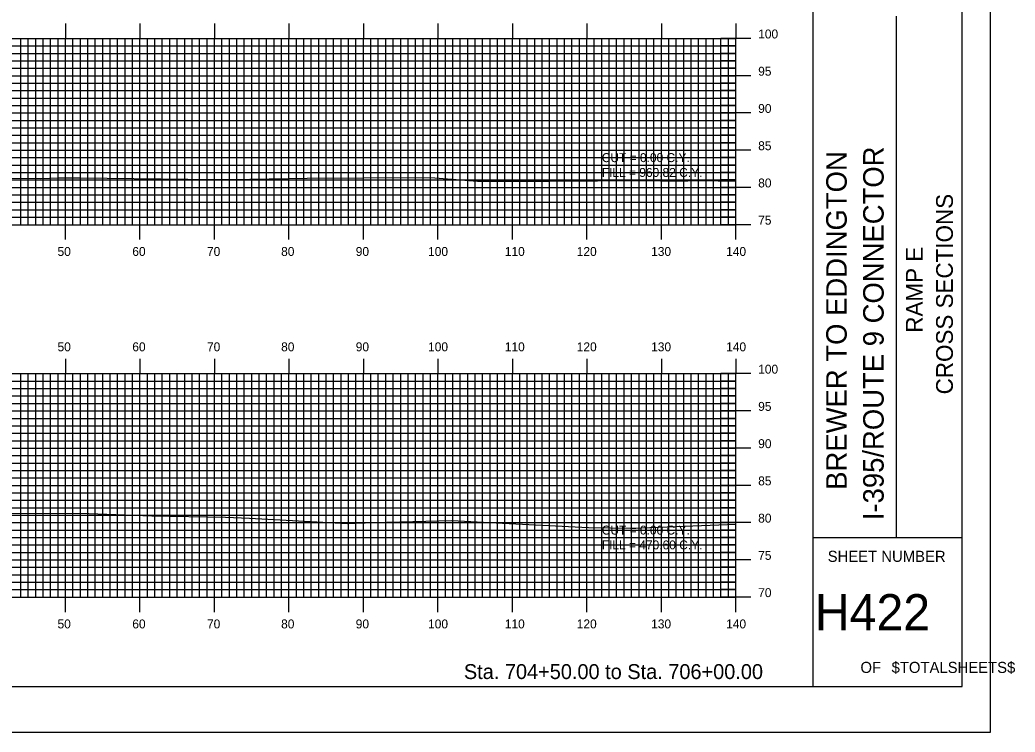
# Model space of a CAD drawing. Extents: x 853723 to 854066, y 364366 to 364586.
# Drawn here: x 853932.6 to 854066.2, y 364365.7 to 364461.3 of the extents above; entities that cross this region are included whole.
import ezdxf

# ---------------------------------------------------------------- set-up
doc = ezdxf.new("R2010")
doc.units = 0
for name, color, linetype in [('BORDER', 7, 'Continuous'), ('D_Text_Standard', 7, 'Continuous'), ('H_V ANNOTATION', 7, 'Continuous'), ('MAJOR', 7, 'Continuous'), ('MINOR', 7, 'Continuous'), ('PLOT BOUNDARY', 7, 'Continuous'), ('S_Roadway_Centerline', 7, 'Continuous')]:
    doc.layers.add(name, color=color, linetype=linetype)

msp = doc.modelspace()

# ---------------------------------------------------------------- linework, layer by layer
at = {"layer": 'BORDER'}
for p, q in [((854039.12, 364371.79), (854039.12, 364581.79)), ((854050.3, 364391.79), (854050.3, 364461.79)), ((854039.12, 364391.79), (854059.12, 364391.79))]:
    msp.add_line(p, q, dxfattribs=at)
msp.add_lwpolyline([(853739.12, 364371.79), (854059.12, 364371.79), (854059.12, 364581.79), (853739.12, 364581.79)], close=True, dxfattribs=at)
at = {"layer": 'MAJOR'}
for p, q in [((853938.72, 364460.79), (853938.72, 364458.79)), ((853948.72, 364460.79), (853948.72, 364458.79)), ((853958.72, 364460.79), (853958.72, 364458.79)), ((853968.72, 364460.79), (853968.72, 364458.79)), ((853978.72, 364460.79), (853978.72, 364458.79)), ((853988.72, 364460.79), (853988.72, 364458.79)), ((853998.72, 364460.79), (853998.72, 364458.79)), ((854008.72, 364460.79), (854008.72, 364458.79)), ((854018.72, 364460.79), (854018.72, 364458.79)), ((854028.72, 364460.79), (854028.72, 364458.79)), ((853748.72, 364458.79), (854028.72, 364458.79)), ((853748.72, 364458.79), (854028.72, 364458.79)), ((853938.72, 364433.79), (853938.72, 364458.79)), ((853948.72, 364433.79), (853948.72, 364458.79)), ((853958.72, 364433.79), (853958.72, 364458.79)), ((853968.72, 364433.79), (853968.72, 364458.79)), ((853978.72, 364433.79), (853978.72, 364458.79)), ((853988.72, 364433.79), (853988.72, 364458.79)), ((853998.72, 364433.79), (853998.72, 364458.79)), ((854008.72, 364433.79), (854008.72, 364458.79)), ((854018.72, 364433.79), (854018.72, 364458.79)), ((854030.72, 364458.79), (854026.71, 364458.79)), ((854028.72, 364433.79), (854028.72, 364458.79)), ((854028.72, 364433.79), (854028.72, 364458.79)), ((853748.72, 364453.79), (854028.72, 364453.79)), ((854030.72, 364453.79), (854026.71, 364453.79)), ((853748.72, 364448.79), (854028.72, 364448.79)), ((854030.72, 364448.79), (854026.71, 364448.79)), ((853748.72, 364443.79), (854028.72, 364443.79)), ((854030.72, 364443.79), (854026.71, 364443.79)), ((853748.72, 364438.79), (854028.72, 364438.79)), ((854030.72, 364438.79), (854026.71, 364438.79)), ((853748.72, 364433.79), (854028.72, 364433.79)), ((853748.72, 364433.79), (854028.72, 364433.79)), ((853938.72, 364431.78), (853938.72, 364433.79)), ((853948.72, 364431.78), (853948.72, 364433.79)), ((853958.72, 364431.78), (853958.72, 364433.79)), ((853968.72, 364431.78), (853968.72, 364433.79)), ((853978.72, 364431.78), (853978.72, 364433.79)), ((853988.72, 364431.78), (853988.72, 364433.79)), ((853998.72, 364431.78), (853998.72, 364433.79)), ((854008.72, 364431.78), (854008.72, 364433.79)), ((854018.72, 364431.78), (854018.72, 364433.79)), ((854030.72, 364433.79), (854026.71, 364433.79)), ((854028.72, 364431.78), (854028.72, 364433.79)), ((853938.72, 364415.79), (853938.72, 364413.79)), ((853948.72, 364415.79), (853948.72, 364413.79)), ((853958.72, 364415.79), (853958.72, 364413.79)), ((853968.72, 364415.79), (853968.72, 364413.79)), ((853978.72, 364415.79), (853978.72, 364413.79)), ((853988.72, 364415.79), (853988.72, 364413.79)), ((853998.72, 364415.79), (853998.72, 364413.79)), ((854008.72, 364415.79), (854008.72, 364413.79)), ((854018.72, 364415.79), (854018.72, 364413.79)), ((854028.72, 364415.79), (854028.72, 364413.79)), ((853748.72, 364413.79), (854028.72, 364413.79)), ((853748.72, 364413.79), (854028.72, 364413.79)), ((853938.72, 364383.79), (853938.72, 364413.79)), ((853948.72, 364383.79), (853948.72, 364413.79)), ((853958.72, 364383.79), (853958.72, 364413.79)), ((853968.72, 364383.79), (853968.72, 364413.79)), ((853978.72, 364383.79), (853978.72, 364413.79)), ((853988.72, 364383.79), (853988.72, 364413.79)), ((853998.72, 364383.79), (853998.72, 364413.79)), ((854008.72, 364383.79), (854008.72, 364413.79)), ((854018.72, 364383.79), (854018.72, 364413.79)), ((854030.72, 364413.79), (854026.71, 364413.79)), ((854028.72, 364383.79), (854028.72, 364413.79)), ((854028.72, 364383.79), (854028.72, 364413.79)), ((853748.72, 364408.79), (854028.72, 364408.79)), ((854030.72, 364408.79), (854026.71, 364408.79)), ((853748.72, 364403.79), (854028.72, 364403.79)), ((854030.72, 364403.79), (854026.71, 364403.79)), ((853748.72, 364398.79), (854028.72, 364398.79)), ((854030.72, 364398.79), (854026.71, 364398.79)), ((853748.72, 364393.79), (854028.72, 364393.79)), ((854030.72, 364393.79), (854026.71, 364393.79)), ((853748.72, 364388.79), (854028.72, 364388.79)), ((854030.72, 364388.79), (854026.71, 364388.79)), ((853748.72, 364383.79), (854028.72, 364383.79)), ((853748.72, 364383.79), (854028.72, 364383.79)), ((853938.72, 364381.78), (853938.72, 364383.79)), ((853948.72, 364381.78), (853948.72, 364383.79)), ((853958.72, 364381.78), (853958.72, 364383.79)), ((853968.72, 364381.78), (853968.72, 364383.79)), ((853978.72, 364381.78), (853978.72, 364383.79)), ((853988.72, 364381.78), (853988.72, 364383.79)), ((853998.72, 364381.78), (853998.72, 364383.79)), ((854008.72, 364381.78), (854008.72, 364383.79)), ((854018.72, 364381.78), (854018.72, 364383.79)), ((854030.72, 364383.79), (854026.71, 364383.79)), ((854028.72, 364381.78), (854028.72, 364383.79))]:
    msp.add_line(p, q, dxfattribs=at)
at = {"layer": 'MINOR'}
for p, q in [((853932.72, 364433.79), (853932.72, 364458.79)), ((853933.72, 364433.79), (853933.72, 364458.79)), ((853934.72, 364433.79), (853934.72, 364458.79)), ((853935.72, 364433.79), (853935.72, 364458.79)), ((853936.72, 364433.79), (853936.72, 364458.79)), ((853937.72, 364433.79), (853937.72, 364458.79)), ((853939.72, 364433.79), (853939.72, 364458.79)), ((853940.72, 364433.79), (853940.72, 364458.79)), ((853941.72, 364433.79), (853941.72, 364458.79)), ((853942.72, 364433.79), (853942.72, 364458.79)), ((853943.72, 364433.79), (853943.72, 364458.79)), ((853944.72, 364433.79), (853944.72, 364458.79)), ((853945.72, 364433.79), (853945.72, 364458.79)), ((853946.72, 364433.79), (853946.72, 364458.79)), ((853947.72, 364433.79), (853947.72, 364458.79)), ((853949.72, 364433.79), (853949.72, 364458.79)), ((853950.72, 364433.79), (853950.72, 364458.79)), ((853951.72, 364433.79), (853951.72, 364458.79)), ((853952.72, 364433.79), (853952.72, 364458.79)), ((853953.72, 364433.79), (853953.72, 364458.79)), ((853954.72, 364433.79), (853954.72, 364458.79)), ((853955.72, 364433.79), (853955.72, 364458.79)), ((853956.72, 364433.79), (853956.72, 364458.79)), ((853957.72, 364433.79), (853957.72, 364458.79)), ((853959.72, 364433.79), (853959.72, 364458.79)), ((853960.72, 364433.79), (853960.72, 364458.79)), ((853961.72, 364433.79), (853961.72, 364458.79)), ((853962.72, 364433.79), (853962.72, 364458.79)), ((853963.72, 364433.79), (853963.72, 364458.79)), ((853964.72, 364433.79), (853964.72, 364458.79)), ((853965.72, 364433.79), (853965.72, 364458.79)), ((853966.72, 364433.79), (853966.72, 364458.79)), ((853967.72, 364433.79), (853967.72, 364458.79)), ((853969.72, 364433.79), (853969.72, 364458.79)), ((853970.72, 364433.79), (853970.72, 364458.79)), ((853971.72, 364433.79), (853971.72, 364458.79)), ((853972.72, 364433.79), (853972.72, 364458.79)), ((853973.72, 364433.79), (853973.72, 364458.79)), ((853974.72, 364433.79), (853974.72, 364458.79)), ((853975.72, 364433.79), (853975.72, 364458.79)), ((853976.72, 364433.79), (853976.72, 364458.79)), ((853977.72, 364433.79), (853977.72, 364458.79)), ((853979.72, 364433.79), (853979.72, 364458.79)), ((853980.72, 364433.79), (853980.72, 364458.79)), ((853981.72, 364433.79), (853981.72, 364458.79)), ((853982.72, 364433.79), (853982.72, 364458.79)), ((853983.72, 364433.79), (853983.72, 364458.79)), ((853984.72, 364433.79), (853984.72, 364458.79)), ((853985.72, 364433.79), (853985.72, 364458.79)), ((853986.72, 364433.79), (853986.72, 364458.79)), ((853987.72, 364433.79), (853987.72, 364458.79)), ((853989.72, 364433.79), (853989.72, 364458.79)), ((853990.72, 364433.79), (853990.72, 364458.79)), ((853991.72, 364433.79), (853991.72, 364458.79)), ((853992.72, 364433.79), (853992.72, 364458.79)), ((853993.72, 364433.79), (853993.72, 364458.79)), ((853994.72, 364433.79), (853994.72, 364458.79)), ((853995.72, 364433.79), (853995.72, 364458.79)), ((853996.72, 364433.79), (853996.72, 364458.79)), ((853997.72, 364433.79), (853997.72, 364458.79)), ((853999.72, 364433.79), (853999.72, 364458.79)), ((854000.72, 364433.79), (854000.72, 364458.79)), ((854001.72, 364433.79), (854001.72, 364458.79)), ((854002.72, 364433.79), (854002.72, 364458.79)), ((854003.72, 364433.79), (854003.72, 364458.79)), ((854004.72, 364433.79), (854004.72, 364458.79)), ((854005.72, 364433.79), (854005.72, 364458.79)), ((854006.72, 364433.79), (854006.72, 364458.79)), ((854007.72, 364433.79), (854007.72, 364458.79)), ((854009.72, 364433.79), (854009.72, 364458.79)), ((854010.72, 364433.79), (854010.72, 364458.79)), ((854011.72, 364433.79), (854011.72, 364458.79)), ((854012.72, 364433.79), (854012.72, 364458.79)), ((854013.72, 364433.79), (854013.72, 364458.79)), ((854014.72, 364433.79), (854014.72, 364458.79)), ((854015.72, 364433.79), (854015.72, 364458.79)), ((854016.72, 364433.79), (854016.72, 364458.79)), ((854017.72, 364433.79), (854017.72, 364458.79)), ((854019.72, 364433.79), (854019.72, 364458.79)), ((854020.72, 364433.79), (854020.72, 364458.79)), ((854021.72, 364433.79), (854021.72, 364458.79)), ((854022.72, 364433.79), (854022.72, 364458.79)), ((854023.72, 364433.79), (854023.72, 364458.79)), ((854024.72, 364433.79), (854024.72, 364458.79)), ((854025.72, 364433.79), (854025.72, 364458.79)), ((854026.72, 364433.79), (854026.72, 364458.79)), ((854027.72, 364433.79), (854027.72, 364458.79)), ((853748.72, 364457.79), (854028.72, 364457.79)), ((853748.72, 364456.79), (854028.72, 364456.79)), ((854028.72, 364457.79), (854026.71, 364457.79)), ((854028.72, 364456.79), (854026.71, 364456.79)), ((853748.72, 364455.79), (854028.72, 364455.79)), ((854028.72, 364455.79), (854026.71, 364455.79)), ((853748.72, 364454.79), (854028.72, 364454.79)), ((854028.72, 364454.79), (854026.71, 364454.79)), ((853748.72, 364452.79), (854028.72, 364452.79)), ((854028.72, 364452.79), (854026.71, 364452.79)), ((853748.72, 364451.79), (854028.72, 364451.79)), ((854028.72, 364451.79), (854026.71, 364451.79)), ((853748.72, 364450.79), (854028.72, 364450.79)), ((854028.72, 364450.79), (854026.71, 364450.79)), ((853748.72, 364449.79), (854028.72, 364449.79)), ((854028.72, 364449.79), (854026.71, 364449.79)), ((853748.72, 364447.79), (854028.72, 364447.79)), ((854028.72, 364447.79), (854026.71, 364447.79)), ((853748.72, 364446.79), (854028.72, 364446.79)), ((854028.72, 364446.79), (854026.71, 364446.79)), ((853748.72, 364445.79), (854028.72, 364445.79)), ((853748.72, 364444.79), (854028.72, 364444.79)), ((854028.72, 364445.79), (854026.71, 364445.79)), ((854028.72, 364444.79), (854026.71, 364444.79)), ((853748.72, 364442.79), (854028.72, 364442.79)), ((854028.72, 364442.79), (854026.71, 364442.79)), ((853748.72, 364441.79), (854028.72, 364441.79)), ((853748.72, 364440.79), (854028.72, 364440.79)), ((854028.72, 364441.79), (854026.71, 364441.79)), ((854028.72, 364440.79), (854026.71, 364440.79)), ((853748.72, 364439.79), (854028.72, 364439.79)), ((854028.72, 364439.79), (854026.71, 364439.79)), ((853748.72, 364437.79), (854028.72, 364437.79)), ((853748.72, 364436.79), (854028.72, 364436.79)), ((854028.72, 364437.79), (854026.71, 364437.79)), ((854028.72, 364436.79), (854026.71, 364436.79)), ((853748.72, 364435.79), (854028.72, 364435.79)), ((854028.72, 364435.79), (854026.71, 364435.79)), ((853748.72, 364434.79), (854028.72, 364434.79)), ((854028.72, 364434.79), (854026.71, 364434.79)), ((853748.72, 364412.79), (854028.72, 364412.79)), ((853932.72, 364383.79), (853932.72, 364413.79)), ((853933.72, 364383.79), (853933.72, 364413.79)), ((853934.72, 364383.79), (853934.72, 364413.79)), ((853935.72, 364383.79), (853935.72, 364413.79)), ((853936.72, 364383.79), (853936.72, 364413.79)), ((853937.72, 364383.79), (853937.72, 364413.79)), ((853939.72, 364383.79), (853939.72, 364413.79)), ((853940.72, 364383.79), (853940.72, 364413.79)), ((853941.72, 364383.79), (853941.72, 364413.79)), ((853942.72, 364383.79), (853942.72, 364413.79)), ((853943.72, 364383.79), (853943.72, 364413.79)), ((853944.72, 364383.79), (853944.72, 364413.79)), ((853945.72, 364383.79), (853945.72, 364413.79)), ((853946.72, 364383.79), (853946.72, 364413.79)), ((853947.72, 364383.79), (853947.72, 364413.79)), ((853949.72, 364383.79), (853949.72, 364413.79)), ((853950.72, 364383.79), (853950.72, 364413.79)), ((853951.72, 364383.79), (853951.72, 364413.79)), ((853952.72, 364383.79), (853952.72, 364413.79)), ((853953.72, 364383.79), (853953.72, 364413.79)), ((853954.72, 364383.79), (853954.72, 364413.79)), ((853955.72, 364383.79), (853955.72, 364413.79)), ((853956.72, 364383.79), (853956.72, 364413.79)), ((853957.72, 364383.79), (853957.72, 364413.79)), ((853959.72, 364383.79), (853959.72, 364413.79)), ((853960.72, 364383.79), (853960.72, 364413.79)), ((853961.72, 364383.79), (853961.72, 364413.79)), ((853962.72, 364383.79), (853962.72, 364413.79)), ((853963.72, 364383.79), (853963.72, 364413.79)), ((853964.72, 364383.79), (853964.72, 364413.79)), ((853965.72, 364383.79), (853965.72, 364413.79)), ((853966.72, 364383.79), (853966.72, 364413.79)), ((853967.72, 364383.79), (853967.72, 364413.79)), ((853969.72, 364383.79), (853969.72, 364413.79)), ((853970.72, 364383.79), (853970.72, 364413.79)), ((853971.72, 364383.79), (853971.72, 364413.79)), ((853972.72, 364383.79), (853972.72, 364413.79)), ((853973.72, 364383.79), (853973.72, 364413.79)), ((853974.72, 364383.79), (853974.72, 364413.79)), ((853975.72, 364383.79), (853975.72, 364413.79)), ((853976.72, 364383.79), (853976.72, 364413.79)), ((853977.72, 364383.79), (853977.72, 364413.79)), ((853979.72, 364383.79), (853979.72, 364413.79)), ((853980.72, 364383.79), (853980.72, 364413.79)), ((853981.72, 364383.79), (853981.72, 364413.79)), ((853982.72, 364383.79), (853982.72, 364413.79)), ((853983.72, 364383.79), (853983.72, 364413.79)), ((853984.72, 364383.79), (853984.72, 364413.79)), ((853985.72, 364383.79), (853985.72, 364413.79)), ((853986.72, 364383.79), (853986.72, 364413.79)), ((853987.72, 364383.79), (853987.72, 364413.79)), ((853989.72, 364383.79), (853989.72, 364413.79)), ((853990.72, 364383.79), (853990.72, 364413.79)), ((853991.72, 364383.79), (853991.72, 364413.79)), ((853992.72, 364383.79), (853992.72, 364413.79)), ((853993.72, 364383.79), (853993.72, 364413.79)), ((853994.72, 364383.79), (853994.72, 364413.79)), ((853995.72, 364383.79), (853995.72, 364413.79)), ((853996.72, 364383.79), (853996.72, 364413.79)), ((853997.72, 364383.79), (853997.72, 364413.79)), ((853999.72, 364383.79), (853999.72, 364413.79)), ((854000.72, 364383.79), (854000.72, 364413.79)), ((854001.72, 364383.79), (854001.72, 364413.79)), ((854002.72, 364383.79), (854002.72, 364413.79)), ((854003.72, 364383.79), (854003.72, 364413.79)), ((854004.72, 364383.79), (854004.72, 364413.79)), ((854005.72, 364383.79), (854005.72, 364413.79)), ((854006.72, 364383.79), (854006.72, 364413.79)), ((854007.72, 364383.79), (854007.72, 364413.79)), ((854009.72, 364383.79), (854009.72, 364413.79)), ((854010.72, 364383.79), (854010.72, 364413.79)), ((854011.72, 364383.79), (854011.72, 364413.79)), ((854012.72, 364383.79), (854012.72, 364413.79)), ((854013.72, 364383.79), (854013.72, 364413.79)), ((854014.72, 364383.79), (854014.72, 364413.79)), ((854015.72, 364383.79), (854015.72, 364413.79)), ((854016.72, 364383.79), (854016.72, 364413.79)), ((854017.72, 364383.79), (854017.72, 364413.79)), ((854019.72, 364383.79), (854019.72, 364413.79)), ((854020.72, 364383.79), (854020.72, 364413.79)), ((854021.72, 364383.79), (854021.72, 364413.79)), ((854022.72, 364383.79), (854022.72, 364413.79)), ((854023.72, 364383.79), (854023.72, 364413.79)), ((854024.72, 364383.79), (854024.72, 364413.79)), ((854025.72, 364383.79), (854025.72, 364413.79)), ((854028.72, 364412.79), (854026.71, 364412.79)), ((854026.72, 364383.79), (854026.72, 364413.79)), ((854027.72, 364383.79), (854027.72, 364413.79)), ((853748.72, 364411.79), (854028.72, 364411.79)), ((854028.72, 364411.79), (854026.71, 364411.79)), ((853748.72, 364410.79), (854028.72, 364410.79)), ((854028.72, 364410.79), (854026.71, 364410.79)), ((853748.72, 364409.79), (854028.72, 364409.79)), ((854028.72, 364409.79), (854026.71, 364409.79)), ((853748.72, 364407.79), (854028.72, 364407.79)), ((854028.72, 364407.79), (854026.71, 364407.79)), ((853748.72, 364406.79), (854028.72, 364406.79)), ((854028.72, 364406.79), (854026.71, 364406.79)), ((853748.72, 364405.79), (854028.72, 364405.79)), ((853748.72, 364404.79), (854028.72, 364404.79)), ((854028.72, 364405.79), (854026.71, 364405.79)), ((854028.72, 364404.79), (854026.71, 364404.79)), ((853748.72, 364402.79), (854028.72, 364402.79)), ((854028.72, 364402.79), (854026.71, 364402.79)), ((853748.72, 364401.79), (854028.72, 364401.79)), ((853748.72, 364400.79), (854028.72, 364400.79)), ((854028.72, 364401.79), (854026.71, 364401.79)), ((854028.72, 364400.79), (854026.71, 364400.79)), ((853748.72, 364399.79), (854028.72, 364399.79)), ((854028.72, 364399.79), (854026.71, 364399.79)), ((853748.72, 364397.79), (854028.72, 364397.79)), ((853748.72, 364396.79), (854028.72, 364396.79)), ((854028.72, 364397.79), (854026.71, 364397.79)), ((854028.72, 364396.79), (854026.71, 364396.79)), ((853748.72, 364395.79), (854028.72, 364395.79)), ((854028.72, 364395.79), (854026.71, 364395.79)), ((853748.72, 364394.79), (854028.72, 364394.79)), ((854028.72, 364394.79), (854026.71, 364394.79)), ((853748.72, 364392.79), (854028.72, 364392.79)), ((854028.72, 364392.79), (854026.71, 364392.79)), ((853748.72, 364391.79), (854028.72, 364391.79)), ((854028.72, 364391.79), (854026.71, 364391.79)), ((853748.72, 364390.79), (854028.72, 364390.79)), ((854028.72, 364390.79), (854026.71, 364390.79)), ((853748.72, 364389.79), (854028.72, 364389.79)), ((854028.72, 364389.79), (854026.71, 364389.79)), ((853748.72, 364387.79), (854028.72, 364387.79)), ((854028.72, 364387.79), (854026.71, 364387.79)), ((853748.72, 364386.79), (854028.72, 364386.79)), ((854028.72, 364386.79), (854026.71, 364386.79)), ((853748.72, 364385.79), (854028.72, 364385.79)), ((853748.72, 364384.79), (854028.72, 364384.79)), ((854028.72, 364385.79), (854026.71, 364385.79)), ((854028.72, 364384.79), (854026.71, 364384.79))]:
    msp.add_line(p, q, dxfattribs=at)
at = {"layer": 'PLOT BOUNDARY'}
msp.add_lwpolyline([(853722.93, 364365.67), (854062.93, 364365.67), (854062.93, 364585.67), (853722.93, 364585.67)], close=True, dxfattribs=at)
at = {"layer": 'S_Roadway_Centerline'}
for points in [[(853922.05, 364440.03), (853935.35, 364440.01), (853937.76, 364440.1), (853940.7, 364440.1), (853955.16, 364439.91), (853960.94, 364439.85), (853971.16, 364440.03), (853978.73, 364440.06), (853987.71, 364440.13), (853994.04, 364439.64), (854003.74, 364439.65), (854016.55, 364439.74), (854020.6, 364439.65), (854023.96, 364439.72), (854028.72, 364439.65)], [(853930.43, 364395), (853940.64, 364395.08), (853950.31, 364394.7), (853960.18, 364394.54), (853963.43, 364394.39), (853976.58, 364393.69), (853980.11, 364393.82), (853990.61, 364394.08), (853997.41, 364393.71), (854008.94, 364393.12), (854014.86, 364393.05), (854026.45, 364393.48), (854028.72, 364393.59)]]:
    msp.add_lwpolyline(points, dxfattribs=at)

# ---------------------------------------------------------------- texts
at = {"layer": 'BORDER'}
for s, height, p in [('I-395/ROUTE 9 CONNECTOR', 2.7557, (854048.57, 364394.12)), ('BREWER TO EDDINGTON', 2.7557, (854043.61, 364398.2)), ('CROSS SECTIONS', 2.25, (854057.86, 364411.01)), ('RAMP E', 2.25, (854053.81, 364419.29))]:
    msp.add_text(s, height=height, rotation=90, dxfattribs=at).set_placement(p)
for s, height, p in [('SHEET NUMBER', 1.4905, (854041.05, 364388.52)), ('H422', 4.839, (854039.33, 364379.35)), ('OF', 1.491, (854045.45, 364373.61)), ('$TOTALSHEETS$', 1.4905, (854049.63, 364373.61))]:
    msp.add_text(s, height=height, dxfattribs=at).set_placement(p)
at = {"layer": 'D_Text_Standard'}
for s, p in [('CUT = 0.00 C.Y.', (854010.72, 364442.19)), ('FILL = 960.82 C.Y.', (854010.72, 364440.2)), ('CUT = 0.00 C.Y.', (854010.72, 364392.19)), ('FILL = 470.60 C.Y.', (854010.72, 364390.2))]:
    msp.add_text(s, height=1.2, dxfattribs=at).set_placement(p)
at = {"layer": 'H_V ANNOTATION'}
for s, height, p in [('100', 1.2, (854031.72, 364458.79)), ('95', 1.2, (854031.72, 364453.79)), ('90', 1.2, (854031.72, 364448.79)), ('85', 1.2, (854031.72, 364443.79)), ('80', 1.2, (854031.72, 364438.79)), ('75', 1.2, (854031.72, 364433.79)), ('50', 1.2, (853937.65, 364429.59)), ('60', 1.2, (853947.69, 364429.59)), ('70', 1.2, (853957.72, 364429.59)), ('80', 1.2, (853967.67, 364429.59)), ('90', 1.2, (853977.69, 364429.59)), ('100', 1.2, (853987.4, 364429.59)), ('110', 1.2, (853997.7, 364429.59)), ('120', 1.2, (854007.36, 364429.59)), ('130', 1.2, (854017.35, 364429.59)), ('140', 1.2, (854027.42, 364429.59)), ('50', 1.2, (853937.65, 364416.79)), ('60', 1.2, (853947.69, 364416.79)), ('70', 1.2, (853957.72, 364416.79)), ('80', 1.2, (853967.67, 364416.79)), ('90', 1.2, (853977.69, 364416.79)), ('100', 1.2, (853987.4, 364416.79)), ('110', 1.2, (853997.7, 364416.79)), ('120', 1.2, (854007.36, 364416.79)), ('130', 1.2, (854017.35, 364416.79)), ('140', 1.2, (854027.42, 364416.79)), ('100', 1.2, (854031.72, 364413.79)), ('95', 1.2, (854031.72, 364408.79)), ('90', 1.2, (854031.72, 364403.79)), ('85', 1.2, (854031.72, 364398.79)), ('80', 1.2, (854031.72, 364393.79)), ('75', 1.2, (854031.72, 364388.79)), ('70', 1.2, (854031.72, 364383.79)), ('50', 1.2, (853937.65, 364379.59)), ('60', 1.2, (853947.69, 364379.59)), ('70', 1.2, (853957.72, 364379.59)), ('80', 1.2, (853967.67, 364379.59)), ('90', 1.2, (853977.69, 364379.59)), ('100', 1.2, (853987.4, 364379.59)), ('110', 1.2, (853997.7, 364379.59)), ('120', 1.2, (854007.36, 364379.59)), ('130', 1.2, (854017.35, 364379.59)), ('140', 1.2, (854027.42, 364379.59)), ('Sta. 704+50.00 to Sta. 706+00.00', 2.0004, (853992.21, 364372.79))]:
    msp.add_text(s, height=height, dxfattribs=at).set_placement(p)

doc.saveas('drawing.dxf')
